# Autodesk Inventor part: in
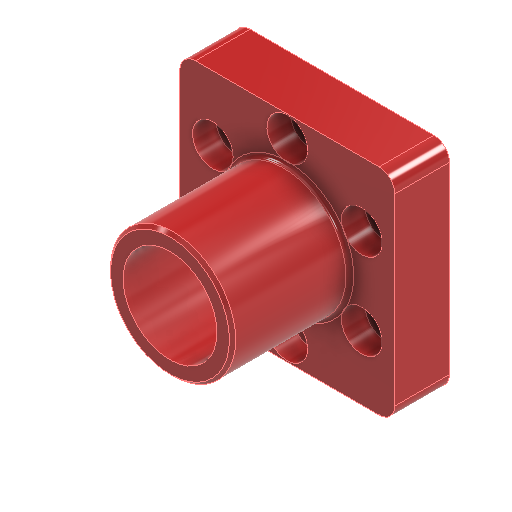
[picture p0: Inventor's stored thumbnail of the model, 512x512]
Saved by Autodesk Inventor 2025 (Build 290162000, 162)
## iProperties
Created: 2025-04
Part Number: in
Material: Plastica PET
Document SubType Name: Modeling
Designer: R5800u
Density: 1.541 g/cm^3
Appearance: Rosso
Author: R5800u
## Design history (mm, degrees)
sketch "Schizzo1"
  geometry: L1 (-0.199, 11.75)-(-0.199, -11.75) reference; L2 (1.801, -13.75)-(25.301, -13.75) reference; L3 (27.301, -11.75)-(27.301, 11.75) reference; L4 (25.301, 13.75)-(1.801, 13.75) reference; C1 r 1.325 at (4.024, 5.5) reference; C2 r 1.325 at (4.024, -5.5) reference; C3 r 1.325 at (13.551, -11) reference; C4 r 1.325 at (23.077, -5.5) reference; C5 r 1.325 at (23.077, 5.5) reference; C6 r 1.325 at (13.551, 11) reference; C7 r 7.551 at (13.551, 0) reference; C8 r 6 at (13.551, 0); A1 r 2 centre (1.801, 11.75) between (1.801, 13.75) and (-0.199, 11.75) reference; A2 r 2 centre (1.801, -11.75) between (-0.199, -11.75) and (1.801, -13.75) reference; A3 r 2 centre (25.301, -11.75) between (25.301, -13.75) and (27.301, -11.75) reference; A4 r 2 centre (25.301, 11.75) between (27.301, 11.75) and (25.301, 13.75) reference; 1 further point
  constraints: 1 centre point, 1 coincident
  dimensions: "d0" = 12 diameter of C8
extrude "Estrusione1" new body sketch "Schizzo1" distance "d1" = 7; taper "d2" = 0 deg
sketch "Schizzo2"
  geometry: C1 r 6 at (13.551, 0) reference; C2 r 6 at (13.551, 0); C3 r 8 at (13.551, 0); 1 further point
  constraints: 2 centre point, 2 coincident
  dimensions: "d3" = 16 diameter of C3
extrude "Estrusione2" join sketch "Schizzo2" distance "d4" = 15; taper "d5" = 0 deg
fillet "Raccordo1" dims "d6" = 0.5
sketch "Schizzo3"
  geometry: C1 r 6 at (-13.551, 0) reference; C2 r 8.5 at (-13.551, 0); 1 further point
  constraints: 1 centre point, 1 coincident
  dimensions: "d7" = 17 diameter of C2
extrude "Estrusione3" cut sketch "Schizzo3" distance "d8" = 1.5; taper "d9" = 0 deg
fillet "Raccordo2" dims "d10" = 1
sketch "Schizzo4"
  geometry: C1 r 1.325 at (4.024, 5.5) reference; C2 r 1.325 at (4.024, -5.5) reference; C3 r 1.325 at (13.551, -11) reference; C4 r 1.325 at (23.077, -5.5) reference; C5 r 1.325 at (13.551, 11) reference; C6 r 1.325 at (23.077, 5.5) reference; 7 further points
  constraints: 6 coincident
hole "Foro1" sketch "Schizzo4" at (4.024, 5.5), (4.024, -5.5), (13.551, -11), (23.077, -5.5), (13.551, 11), (23.077, 5.5) diameter "d11" = 2.5; stored, may be unused: countersink angle "d15" = 90 deg, drill point angle "d17" = 118 deg; dims "d12" = 6, "d13" = 5.2, "d14" = 3, "d16" = 8
chamfer "Smusso1" distance "d18" = 0.4; stored, may be unused: second distance "d19" = 2, angle "d20" = 45 deg
node "Solido1"
node "Riferimento1"
